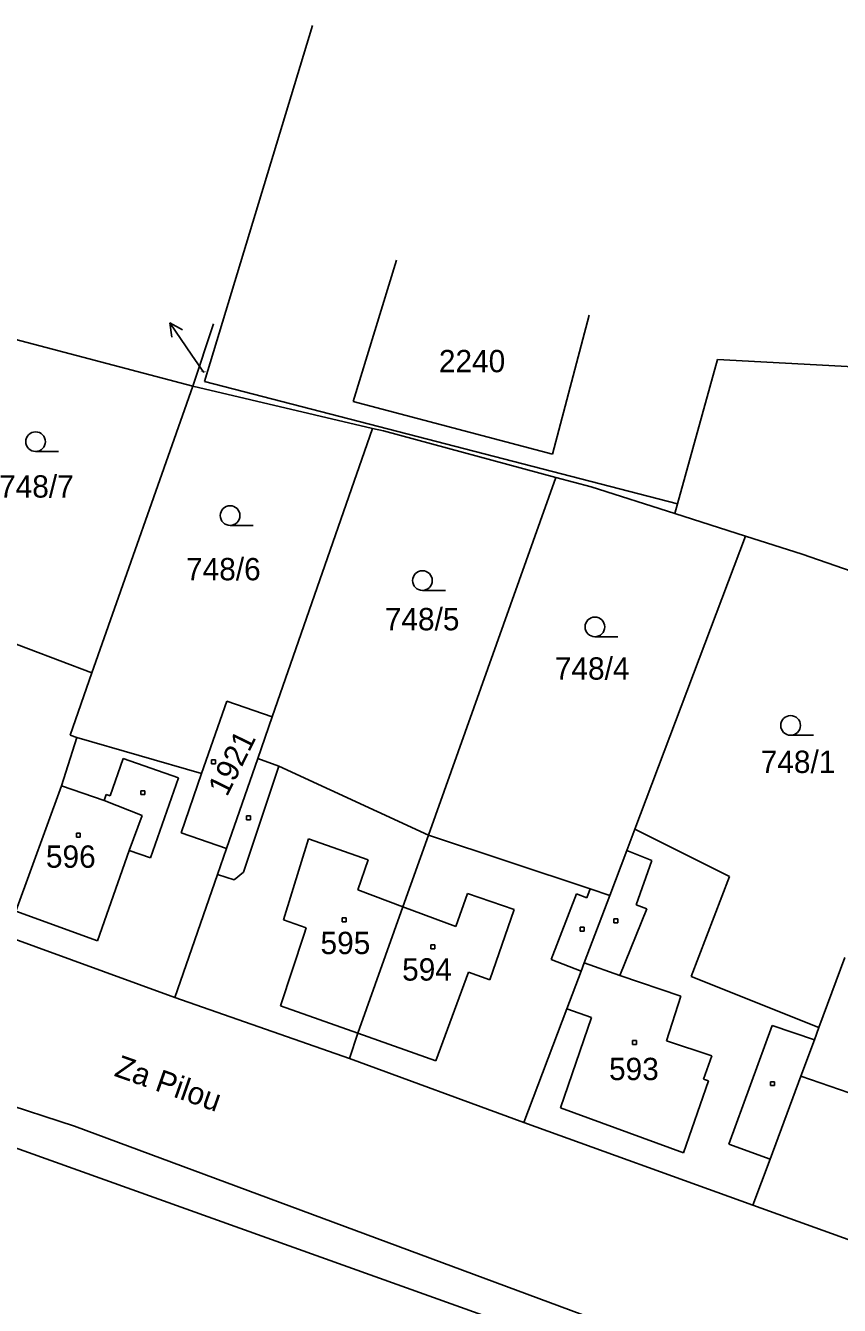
# Model space of a CAD drawing. Extents: x -711879 to -711361, y -1048782 to -1048177.
# Drawn here: x -711646.6 to -711584.5, y -1048304.3 to -1048206.8 of the extents above; entities that cross this region are included whole.
import ezdxf

# ---------------------------------------------------------------- set-up
doc = ezdxf.new("R2010")
doc.units = 0
for name, color, linetype in [('Vrstva 1', 7, 'Continuous'), ('Vrstva 13', 7, 'Continuous'), ('Vrstva 14', 7, 'Continuous'), ('Vrstva 15', 7, 'Continuous'), ('Vrstva 16', 7, 'Continuous'), ('Vrstva 2', 7, 'Continuous'), ('Vrstva 23', 7, 'Continuous'), ('Vrstva 25', 7, 'Continuous'), ('Vrstva 38', 7, 'Continuous'), ('Vrstva 46', 7, 'Continuous')]:
    doc.layers.add(name, color=color, linetype=linetype)

msp = doc.modelspace()

# ---------------------------------------------------------------- linework, layer by layer
at = {"layer": 'Vrstva 1'}
for p, q in [((-711624.67, -1048206.84), (-711632.92, -1048233.95)), ((-711621.57, -1048235.47), (-711618.27, -1048224.7)), ((-711603.59, -1048228.91), (-711606.38, -1048239.48)), ((-711650.65, -1048229.88), (-711633.81, -1048234.32)), ((-711633.81, -1048234.32), (-711632.23, -1048229.57)), ((-711596.86, -1048243.27), (-711593.81, -1048232.28)), ((-711593.81, -1048232.28), (-711583.46, -1048232.83)), ((-711641.49, -1048256.16), (-711633.81, -1048234.32)), ((-711620.1, -1048237.53), (-711633.81, -1048234.32)), ((-711632.92, -1048233.95), (-711596.86, -1048243.27)), ((-711606.38, -1048239.48), (-711621.57, -1048235.47)), ((-711620.1, -1048237.53), (-711627.76, -1048259.5)), ((-711619.27, -1048237.72), (-711620.1, -1048237.53)), ((-711606.13, -1048241.27), (-711619.27, -1048237.72)), ((-711615.84, -1048268.52), (-711606.13, -1048241.27)), ((-711603.45, -1048241.99), (-711606.13, -1048241.27)), ((-711597.06, -1048244.01), (-711603.45, -1048241.99)), ((-711596.86, -1048243.27), (-711597.06, -1048244.01)), ((-711591.68, -1048245.73), (-711597.06, -1048244.01)), ((-711600.12, -1048268.05), (-711591.68, -1048245.73)), ((-711587.36, -1048247.11), (-711591.68, -1048245.73)), ((-711577.43, -1048250.58), (-711587.36, -1048247.11)), ((-711652.61, -1048251.93), (-711641.49, -1048256.16)), ((-711643.14, -1048260.9), (-711641.49, -1048256.16)), ((-711631.21, -1048258.3), (-711633.13, -1048263.83)), ((-711627.76, -1048259.5), (-711631.21, -1048258.3)), ((-711628.86, -1048262.67), (-711627.76, -1048259.5)), ((-711643.82, -1048264.75), (-711642.65, -1048261.08)), ((-711642.65, -1048261.08), (-711643.14, -1048260.9)), ((-711642.65, -1048261.08), (-711633.13, -1048263.83)), ((-711631.24, -1048269.54), (-711628.86, -1048262.67)), ((-711628.86, -1048262.67), (-711627.24, -1048263.25)), ((-711627.24, -1048263.25), (-711615.84, -1048268.52)), ((-711633.13, -1048263.83), (-711634.7, -1048268.34)), ((-711647.29, -1048274.32), (-711643.82, -1048264.75)), ((-711634.7, -1048268.34), (-711631.24, -1048269.54)), ((-711600.73, -1048269.68), (-711600.12, -1048268.05)), ((-711592.89, -1048271.68), (-711600.12, -1048268.05)), ((-711617.79, -1048273.98), (-711615.84, -1048268.52)), ((-711615.84, -1048268.52), (-711603.52, -1048272.62)), ((-711631.24, -1048269.54), (-711631.92, -1048271.52)), ((-711602.03, -1048273.12), (-711600.73, -1048269.68)), ((-711631.92, -1048271.52), (-711635.17, -1048280.88)), ((-711592.89, -1048271.68), (-711595.83, -1048279.29)), ((-711603.97, -1048278.25), (-711602.03, -1048273.12)), ((-711603.52, -1048272.62), (-711602.03, -1048273.12)), ((-711621.22, -1048283.61), (-711617.79, -1048273.98)), ((-711635.17, -1048280.88), (-711648.51, -1048276.04)), ((-711586.08, -1048283.18), (-711584.1, -1048277.85)), ((-711605.29, -1048281.75), (-711604.21, -1048278.89)), ((-711604.21, -1048278.89), (-711603.97, -1048278.25)), ((-711595.83, -1048279.29), (-711586.08, -1048283.18)), ((-711621.86, -1048285.54), (-711635.17, -1048280.88)), ((-711608.57, -1048290.42), (-711605.29, -1048281.75)), ((-711621.22, -1048283.61), (-711621.86, -1048285.54)), ((-711586.43, -1048284.11), (-711586.08, -1048283.18)), ((-711660.45, -1048284.99), (-711642.81, -1048290.69)), ((-711587.46, -1048286.88), (-711586.43, -1048284.11)), ((-711608.57, -1048290.42), (-711621.86, -1048285.54)), ((-711589.81, -1048293.21), (-711587.46, -1048286.88)), ((-711642.81, -1048290.69), (-711594.43, -1048308.63)), ((-711591.11, -1048296.7), (-711608.57, -1048290.42)), ((-711591.11, -1048296.7), (-711589.81, -1048293.21)), ((-711576.93, -1048301.82), (-711591.11, -1048296.7))]:
    msp.add_line(p, q, dxfattribs=at)
at = {"layer": 'Vrstva 13'}
msp.add_line((-711632.97, -1048233.26), (-711633.87, -1048231.95), dxfattribs=at)
at = {"layer": 'Vrstva 16'}
for p, q in [((-711633.87, -1048231.95), (-711635.562, -1048229.473)), ((-711635.562, -1048229.473), (-711635.411, -1048230.58)), ((-711635.562, -1048229.473), (-711634.585, -1048230.016))]:
    msp.add_line(p, q, dxfattribs=at)
at = {"layer": 'Vrstva 2'}
for p, q in [((-711639.11, -1048262.68), (-711640.11, -1048265.51)), ((-711634.9, -1048264.16), (-711639.11, -1048262.68)), ((-711627.24, -1048263.25), (-711629.94, -1048271.35)), ((-711637.04, -1048270.25), (-711634.9, -1048264.16)), ((-711640.57, -1048265.89), (-711643.82, -1048264.75)), ((-711640.4, -1048265.42), (-711640.57, -1048265.89)), ((-711640.11, -1048265.51), (-711640.4, -1048265.42)), ((-711640.57, -1048265.89), (-711637.66, -1048267.03)), ((-711637.66, -1048267.03), (-711638.66, -1048269.68)), ((-711626.89, -1048274.96), (-711624.99, -1048268.8)), ((-711624.99, -1048268.8), (-711620.45, -1048270.39)), ((-711638.66, -1048269.68), (-711641.08, -1048276.57)), ((-711638.66, -1048269.68), (-711637.04, -1048270.25)), ((-711620.45, -1048270.39), (-711621.22, -1048272.69)), ((-711598.83, -1048270.46), (-711600.73, -1048269.68)), ((-711629.94, -1048271.35), (-711630.65, -1048271.93)), ((-711600.01, -1048273.82), (-711598.83, -1048270.46)), ((-711630.65, -1048271.93), (-711631.92, -1048271.52)), ((-711621.22, -1048272.69), (-711617.79, -1048273.98)), ((-711613.76, -1048275.49), (-711612.88, -1048272.96)), ((-711609.3, -1048274.17), (-711612.88, -1048272.96)), ((-711606.5, -1048277.99), (-711604.56, -1048272.99)), ((-711604.56, -1048272.99), (-711603.77, -1048273.29)), ((-711603.77, -1048273.29), (-711603.52, -1048272.62)), ((-711617.79, -1048273.98), (-711613.76, -1048275.49)), ((-711611.16, -1048279.54), (-711609.3, -1048274.17)), ((-711601.25, -1048279.21), (-711599.2, -1048274.14)), ((-711599.2, -1048274.14), (-711600.01, -1048273.82)), ((-711641.08, -1048276.57), (-711647.29, -1048274.32)), ((-711626.89, -1048274.96), (-711625.17, -1048275.58)), ((-711625.32, -1048276.05), (-711627.13, -1048281.52)), ((-711625.17, -1048275.58), (-711625.32, -1048276.05)), ((-711606.5, -1048277.99), (-711604.21, -1048278.89)), ((-711615.27, -1048285.71), (-711612.79, -1048278.95)), ((-711612.79, -1048278.95), (-711611.16, -1048279.54)), ((-711601.25, -1048279.21), (-711603.97, -1048278.25)), ((-711596.62, -1048280.78), (-711601.25, -1048279.21)), ((-711597.7, -1048284.19), (-711596.62, -1048280.78)), ((-711627.13, -1048281.52), (-711621.22, -1048283.61)), ((-711603.41, -1048282.4), (-711605.29, -1048281.75)), ((-711605.78, -1048289.29), (-711603.41, -1048282.4)), ((-711592.94, -1048292.05), (-711589.65, -1048283.01)), ((-711589.65, -1048283.01), (-711586.43, -1048284.11)), ((-711621.22, -1048283.61), (-711615.27, -1048285.71)), ((-711594.24, -1048285.33), (-711597.7, -1048284.19)), ((-711594.89, -1048287.1), (-711594.24, -1048285.33)), ((-711587.46, -1048286.88), (-711581.79, -1048288.85)), ((-711660.67, -1048287.56), (-711603.88, -1048307.87)), ((-711596.4, -1048292.72), (-711594.51, -1048287.23)), ((-711594.51, -1048287.23), (-711594.89, -1048287.1)), ((-711605.78, -1048289.29), (-711596.4, -1048292.72)), ((-711592.94, -1048292.05), (-711589.81, -1048293.21))]:
    msp.add_line(p, q, dxfattribs=at)
at = {"layer": 'Vrstva 23'}
for p, q in [((-711645.79, -1048239.29), (-711644.04, -1048239.29)), ((-711630.96, -1048244.92), (-711629.21, -1048244.92)), ((-711616.3, -1048249.87), (-711614.55, -1048249.87)), ((-711603.16, -1048253.4), (-711601.41, -1048253.4)), ((-711588.24, -1048260.91), (-711586.49, -1048260.91))]:
    msp.add_line(p, q, dxfattribs=at)
for centre in [(-711645.79, -1048238.54), (-711630.96, -1048244.17), (-711616.3, -1048249.12), (-711603.16, -1048252.65), (-711588.24, -1048260.16)]:
    msp.add_circle(centre, 0.75, dxfattribs=at)
at = {"layer": 'Vrstva 25'}
for p, q in [((-711632.37, -1048262.79), (-711632.07, -1048262.79)), ((-711632.37, -1048263.09), (-711632.37, -1048262.79)), ((-711632.07, -1048263.09), (-711632.37, -1048263.09)), ((-711632.07, -1048262.79), (-711632.07, -1048263.09)), ((-711637.77, -1048265.13), (-711637.47, -1048265.13)), ((-711637.77, -1048265.43), (-711637.77, -1048265.13)), ((-711637.47, -1048265.43), (-711637.77, -1048265.43)), ((-711637.47, -1048265.13), (-711637.47, -1048265.43)), ((-711629.7, -1048267.05), (-711629.4, -1048267.05)), ((-711629.7, -1048267.35), (-711629.7, -1048267.05)), ((-711629.4, -1048267.35), (-711629.7, -1048267.35)), ((-711629.4, -1048267.05), (-711629.4, -1048267.35)), ((-711642.68, -1048268.37), (-711642.38, -1048268.37)), ((-711642.68, -1048268.67), (-711642.68, -1048268.37)), ((-711642.38, -1048268.37), (-711642.38, -1048268.67)), ((-711642.38, -1048268.67), (-711642.68, -1048268.67)), ((-711622.42, -1048274.81), (-711622.12, -1048274.81)), ((-711622.42, -1048275.11), (-711622.42, -1048274.81)), ((-711622.12, -1048275.11), (-711622.42, -1048275.11)), ((-711622.12, -1048274.81), (-711622.12, -1048275.11)), ((-711601.71, -1048274.9), (-711601.41, -1048274.9)), ((-711601.71, -1048275.2), (-711601.71, -1048274.9)), ((-711601.41, -1048275.2), (-711601.71, -1048275.2)), ((-711601.41, -1048274.9), (-711601.41, -1048275.2)), ((-711604.28, -1048275.53), (-711603.98, -1048275.53)), ((-711604.28, -1048275.83), (-711604.28, -1048275.53)), ((-711603.98, -1048275.83), (-711604.28, -1048275.83)), ((-711603.98, -1048275.53), (-711603.98, -1048275.83)), ((-711615.67, -1048276.88), (-711615.37, -1048276.88)), ((-711615.67, -1048277.18), (-711615.67, -1048276.88)), ((-711615.37, -1048277.18), (-711615.67, -1048277.18)), ((-711615.37, -1048276.88), (-711615.37, -1048277.18)), ((-711600.28, -1048284.17), (-711599.98, -1048284.17)), ((-711600.28, -1048284.47), (-711600.28, -1048284.17)), ((-711599.98, -1048284.47), (-711600.28, -1048284.47)), ((-711599.98, -1048284.17), (-711599.98, -1048284.47)), ((-711589.78, -1048287.3), (-711589.48, -1048287.3)), ((-711589.78, -1048287.6), (-711589.78, -1048287.3)), ((-711589.48, -1048287.6), (-711589.78, -1048287.6)), ((-711589.48, -1048287.3), (-711589.48, -1048287.6))]:
    msp.add_line(p, q, dxfattribs=at)
at = {"layer": 'Vrstva 46'}
for p, q in [((-711593.81, -1048232.28), (-711593.81, -1048232.28)), ((-711633.81, -1048234.32), (-711633.81, -1048234.32)), ((-711620.1, -1048237.53), (-711620.1, -1048237.53)), ((-711619.27, -1048237.72), (-711619.27, -1048237.72)), ((-711606.13, -1048241.27), (-711606.13, -1048241.27)), ((-711603.45, -1048241.99), (-711603.45, -1048241.99)), ((-711597.06, -1048244.01), (-711597.06, -1048244.01)), ((-711596.86, -1048243.27), (-711596.86, -1048243.27)), ((-711587.36, -1048247.11), (-711587.36, -1048247.11)), ((-711627.76, -1048259.5), (-711627.76, -1048259.5)), ((-711643.82, -1048264.75), (-711643.82, -1048264.75)), ((-711640.57, -1048265.89), (-711640.57, -1048265.89)), ((-711637.66, -1048267.03), (-711637.66, -1048267.03)), ((-711638.66, -1048269.68), (-711638.66, -1048269.68)), ((-711631.24, -1048269.54), (-711631.24, -1048269.54)), ((-711592.89, -1048271.68), (-711592.89, -1048271.68)), ((-711626.89, -1048274.96), (-711626.89, -1048274.96)), ((-711625.32, -1048276.05), (-711625.32, -1048276.05)), ((-711625.17, -1048275.58), (-711625.17, -1048275.58)), ((-711641.08, -1048276.57), (-711641.08, -1048276.57)), ((-711606.5, -1048277.99), (-711606.5, -1048277.99)), ((-711612.79, -1048278.95), (-711612.79, -1048278.95)), ((-711611.16, -1048279.54), (-711611.16, -1048279.54)), ((-711635.17, -1048280.88), (-711635.17, -1048280.88)), ((-711627.13, -1048281.52), (-711627.13, -1048281.52)), ((-711621.22, -1048283.61), (-711621.22, -1048283.61)), ((-711586.08, -1048283.18), (-711586.08, -1048283.18)), ((-711621.86, -1048285.54), (-711621.86, -1048285.54)), ((-711615.27, -1048285.71), (-711615.27, -1048285.71)), ((-711587.46, -1048286.88), (-711587.46, -1048286.88)), ((-711605.78, -1048289.29), (-711605.78, -1048289.29)), ((-711642.81, -1048290.69), (-711642.81, -1048290.69)), ((-711596.4, -1048292.72), (-711596.4, -1048292.72)), ((-711592.94, -1048292.05), (-711592.94, -1048292.05)), ((-711589.81, -1048293.21), (-711589.81, -1048293.21))]:
    msp.add_line(p, q, dxfattribs=at)

# ---------------------------------------------------------------- texts
at = {"layer": 'Vrstva 14'}
for s, height, p in [('741/49', 0.1, (-711633.207, -1048233.26)), ('748/7', 1.7, (-711648.57, -1048242.8)), ('748/6', 1.7, (-711634.32, -1048249.1)), ('748/5', 1.7, (-711619.17, -1048252.91)), ('748/4', 1.7, (-711606.21, -1048256.67)), ('748/1', 1.7, (-711590.52, -1048263.78))]:
    msp.add_text(s, height=height, dxfattribs=at).set_placement(p)
at = {"layer": 'Vrstva 15'}
for s, p in [('2240', (-711615.05, -1048233.25)), ('596', (-711645, -1048271)), ('595', (-711624.07, -1048277.58)), ('594', (-711617.85, -1048279.6)), ('593', (-711602.08, -1048287.18))]:
    msp.add_text(s, height=1.7, dxfattribs=at).set_placement(p)
msp.add_text('1921', height=1.7, rotation=63.63117, dxfattribs=at).set_placement((-711631.2, -1048265.65))
at = {"layer": 'Vrstva 38'}
msp.add_text('Za Pilou', height=1.7, rotation=340.5429, dxfattribs=at).set_placement((-711639.87, -1048286.84))

doc.saveas('drawing.dxf')
